// Mitsubishi GX Works2 project: FX3G_COM2_modbus从机   PLC: FX3G

PROGRAM MAIN
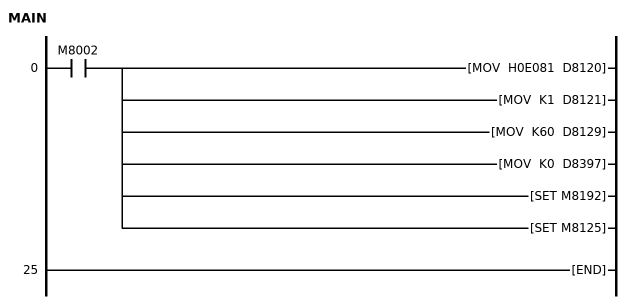
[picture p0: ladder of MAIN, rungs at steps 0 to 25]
0     LD      M8002
      MOV     H0E081 D8120
        [note] 通讯设定9600 8 N 1
      MOV     K1 D8121
        [note] 站号设定
      MOV     K60 D8129
        [note] RD3A通讯超时设定
      MOV     K0 D8397
      SET     M8192
      SET     M8125
25    END
END_PROGRAM

// device comments not shown above
D200  ; 写入数量，1个
D211  ; 转速
M2  ; 反转
M3  ; 停止
